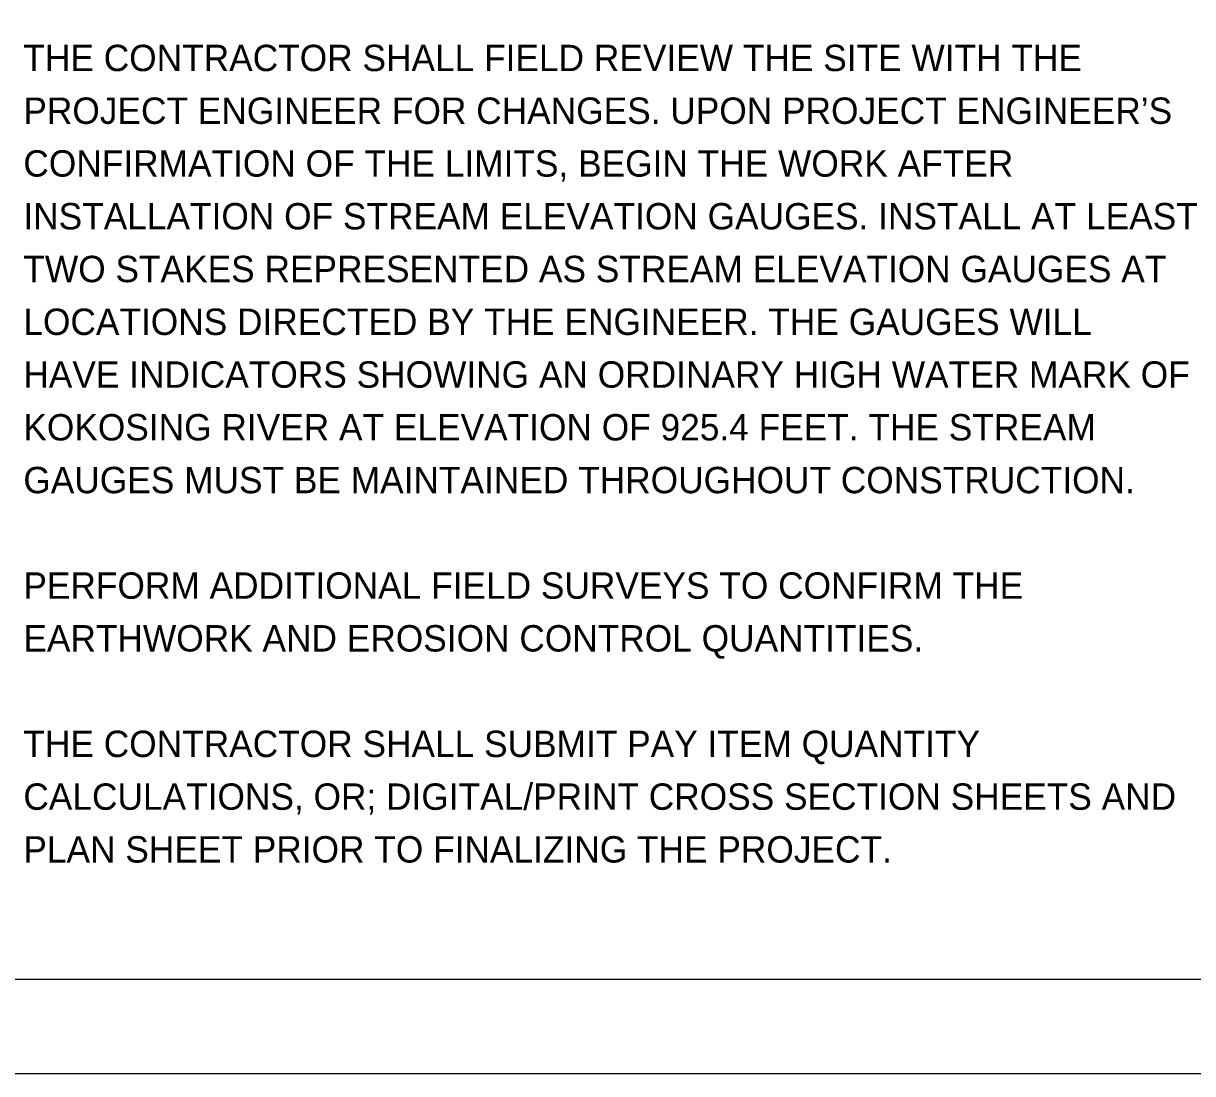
# Model space of a CAD drawing. Extents: x 0 to 58.9, y 0 to 22.
# Drawn here: x 24.66 to 30.86, y 0 to 5.57 of the extents above; entities that cross this region are included whole.
import ezdxf

# ---------------------------------------------------------------- set-up
doc = ezdxf.new("R2010")
doc.units = 0
for name, color, linetype in [('CS-ALGN-CNTR', 7, 'Continuous'), ('CS-ALGN-TEXT', 7, 'Continuous'), ('CS-ANNO-MATC', 7, 'Continuous')]:
    doc.layers.add(name, color=color, linetype=linetype)

msp = doc.modelspace()

# ---------------------------------------------------------------- linework, layer by layer
at = {"layer": 'CS-ALGN-CNTR'}
msp.add_lwpolyline([(0, 0), (34, 0), (34, 22), (0, 22)], close=True, dxfattribs=at)
at = {"layer": 'CS-ALGN-TEXT'}
msp.add_lwpolyline([(1.5, 21.5), (33.5, 21.5), (33.5, 0.5), (1.5, 0.5)], close=True, dxfattribs=at)

# ---------------------------------------------------------------- texts
at = {"layer": 'CS-ANNO-MATC'}
for s, p in [('THE CONTRACTOR SHALL FIELD REVIEW THE SITE WITH THE ', (24.66, 5.32)), ('PROJECT ENGINEER FOR CHANGES. UPON PROJECT ENGINEER’S ', (24.66, 5.04)), ('CONFIRMATION OF THE LIMITS, BEGIN THE WORK AFTER ', (24.66, 4.76)), ('INSTALLATION OF STREAM ELEVATION GAUGES. INSTALL AT LEAST ', (24.66, 4.48)), ('TWO STAKES REPRESENTED AS STREAM ELEVATION GAUGES AT ', (24.66, 4.2)), ('LOCATIONS DIRECTED BY THE ENGINEER. THE GAUGES WILL ', (24.66, 3.92)), ('HAVE INDICATORS SHOWING AN ORDINARY HIGH WATER MARK OF ', (24.66, 3.64)), ('KOKOSING RIVER AT ELEVATION OF 925.4 FEET. THE STREAM ', (24.66, 3.36)), ('GAUGES MUST BE MAINTAINED THROUGHOUT CONSTRUCTION.', (24.66, 3.08)), ('PERFORM ADDITIONAL FIELD SURVEYS TO CONFIRM THE ', (24.66, 2.52)), ('EARTHWORK AND EROSION CONTROL QUANTITIES.', (24.66, 2.24)), ('THE CONTRACTOR SHALL SUBMIT PAY ITEM QUANTITY ', (24.66, 1.68)), ('CALCULATIONS, OR; DIGITAL/PRINT CROSS SECTION SHEETS AND ', (24.66, 1.4)), ('PLAN SHEET PRIOR TO FINALIZING THE PROJECT.', (24.66, 1.12))]:
    msp.add_text(s, height=0.14, dxfattribs=at).set_placement(p)

doc.saveas('drawing.dxf')
